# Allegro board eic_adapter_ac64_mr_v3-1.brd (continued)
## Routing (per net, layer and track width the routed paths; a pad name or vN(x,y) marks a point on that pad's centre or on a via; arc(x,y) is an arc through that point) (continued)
SIPMOUT39: length 24.3
  TOP w0.2: J4.35 v1(22.2,65) ; v1(21.4,54.3) Q3.8
  TOP w0.25: C80.2 v1(22.9,47.98)
  LAYER_6 w0.2: v1(22.9,47.98) 21.4,49.48 v1(21.4,54.3) 21.4,55 21.7,55.3 21.7,61.3 21.2,61.8 21.2,62.7 21.8,63.3 21.8,64.09 22.2,64.49 v1(22.2,65)
  BOTTOM w0.25: v1(22.9,47.98) R107.2
SIPMOUT40: length 23.6
  TOP w0.2: v1(32.2,62.5) J4.10 32.2,60.1 33,59.3 Q2.3
  TOP w0.25: C81.2 v1(35.3,46.72)
  LAYER_2 w0.2: v1(35.3,46.72) 34.69,46.72 32,49.4 32,55.9 32.2,56.1 v1(32.2,62.5)
  BOTTOM w0.25: v1(35.3,46.72) R111.2
SIPMOUT41: length 24.4
  TOP w0.2: v1(22.6,63.4) J4.34 22.6,60.1 21.8,59.3 Q3.2
  TOP w0.25: C82.2 v1(22.9,46.72)
  LAYER_8 w0.2: v1(22.6,63.4) 22.6,55.6 23.7,54.5 23.7,47.52 v1(22.9,46.72)
  BOTTOM w0.25: v1(22.9,46.72) R115.2
SIPMOUT42: length 28.6
  TOP w0.2: J4.11 v1(31.8,65) ; v1(32.6,54.9) 32.6,55.41 33,55.81 Q2.8
  TOP w0.25: C83.2 v1(35.2,44.17)
  LAYER_6 w0.2: v1(35.2,44.17) 34.62,44.17 32.6,46.2 v1(32.6,54.9) 32.6,58.7 31.5,59.8 31.5,62.6 32.2,63.3 32.2,63.8 31.8,64.2 v1(31.8,65)
  BOTTOM w0.25: v1(35.2,44.17) R119.2
SIPMOUT43: length 28.5
  TOP w0.2: v1(22.8,54.4) 22.8,54.9 21.8,55.9 Q3.9 ; J4.33 v1(23,65.5)
  TOP w0.25: C84.2 v1(23,44.17)
  LAYER_2 w0.2: v1(23,44.17) 23.9,45.08 23.9,52.8 22.8,53.9 v1(22.8,54.4) 22.8,55.3 22.5,55.6 22.5,62.4 23.4,63.3 23.4,64 23,64.4 v1(23,65.5)
  BOTTOM w0.25: v1(23,44.17) R123.2
SIPMOUT44: length 29.5
  TOP w0.2: v1(31.4,63.4) J4.12 31.4,60.1 32.6,58.9 Q2.4
  TOP w0.25: C85.2 v1(35.2,42.91)
  LAYER_8 w0.2: v1(31.4,63.4) 31.4,59.5 31.9,59 31.9,45.5 34.49,42.91 v1(35.2,42.91)
  BOTTOM w0.25: v1(35.2,42.91) R127.2
SIPMOUT45: length 27.4
  TOP w0.2: v1(23.4,62.5) J4.32 23.4,59.9 22.2,58.7 Q3.1
  TOP w0.25: C86.2 v1(23,42.91)
  LAYER_6 w0.2: v1(23.4,62.5) 23.4,59.4 22.7,58.7 22.7,55.5 23.6,54.6 23.6,53.3 24.2,52.7 24.2,43.6 23.51,42.91 v1(23,42.91)
  BOTTOM w0.25: v1(23,42.91) R131.2
SIPMOUT46: length 32.3
  TOP w0.2: J4.13 v1(31,65.5) ; v1(31.3,55.3) 31.81,55.3 32.6,56.09 Q2.7
  TOP w0.25: C87.2 v1(35.3,41.63)
  LAYER_2 w0.2: v1(31,65.5) 31,64.4 30.6,64 30.6,63.3 31.3,62.6 31.3,61 30.5,60.2 30.5,56.1 v1(31.3,55.3) 31.3,44.9 34.56,41.63 v1(35.3,41.63)
  BOTTOM w0.25: v1(35.3,41.63) R135.2
SIPMOUT47: length 30.9
  TOP w0.2: Q3.10 22.2,56.6 22.4,56.4 v1(23.4,56.4) ; J4.31 v1(23.8,65)
  TOP w0.25: C88.2 v1(22.99,41.63)
  LAYER_6 w0.2: v1(22.99,41.63) 23.03,41.6 23.6,41.6 24.9,42.9 24.9,53.4 24.6,53.7 24.6,55.8 24,56.4 ; v1(23.4,56.4) 24,56.4 ; 24,56.4 24.2,56.6 24.2,62.5 23.5,63.2 23.5,64.1 23.8,64.4 v1(23.8,65)
  BOTTOM w0.25: v1(22.99,41.63) R139.2
SIPMOUT48: length 30.2
  TOP w0.2: Q4.1 30.2,59.6 30.6,60 J4.14 v1(30.6,62.5)
  TOP w0.25: C89.2 v1(35.2,40.37)
  LAYER_6 w0.2: v1(35.2,40.37) 34.63,40.37 31.9,43.1 31.9,58.5 30.6,59.8 v1(30.6,62.5)
  BOTTOM w0.25: v1(35.2,40.37) R81.2
SIPMOUT49: length 31
  TOP w0.2: Q5.4 24.9,59.1 24.2,59.8 J4.30 v1(24.2,63.4)
  TOP w0.25: C90.2 v1(22.99,40.37)
  LAYER_8 w0.2: v1(22.99,40.37) 23.57,40.37 24.6,41.4 24.6,60.9 24.2,61.3 v1(24.2,63.4)
  BOTTOM w0.25: v1(22.99,40.37) R85.2
SIPMOUT50: length 34.3
  TOP w0.2: v1(31.2,56.3) 31.1,56.2 30.6,56.2 30.2,56.6 Q4.10 ; J4.15 v1(30.2,65)
  TOP w0.25: C91.2 v1(35.2,39.09)
  LAYER_6 w0.2: v1(31.2,56.3) 30.7,56.3 ; 30.7,56.3 29.8,57.2 29.8,62.5 30.6,63.3 30.6,63.9 30.2,64.3 v1(30.2,65) ; 30.7,56.3 30.65,56.25 30.65,54.7 31.23,54.12 31.23,42.56 34.69,39.09 v1(35.2,39.09)
  BOTTOM w0.25: v1(35.2,39.09) R89.2
SIPMOUT51: length 33.4
  TOP w0.2: v1(23.9,55.3) 24.64,56.04 24.64,56.34 24.9,56.6 Q5.7 ; J4.29 v1(24.6,65.5)
  TOP w0.25: C92.2 v1(23,39.09)
  LAYER_2 w0.2: v1(23,39.09) 23.5,39.09 25,40.59 25,53.4 23.9,54.5 v1(23.9,55.3) 23.9,55.8 24.25,56.16 24.25,62.55 25,63.3 25,64 24.6,64.4 v1(24.6,65.5)
  BOTTOM w0.25: v1(23,39.09) R93.2
SIPMOUT52: length 34.7
  TOP w0.2: v1(29.8,63.4) J4.16 Q4.2
  TOP w0.25: C93.2 v1(35.2,37.83)
  LAYER_8 w0.2: v1(29.8,63.4) 29.8,56.7 30.7,55.8 30.7,41.7 34.58,37.83 v1(35.2,37.83)
  BOTTOM w0.25: v1(35.2,37.83) R97.2
SIPMOUT53: length 32.4
  TOP w0.2: v1(25,62.5) J4.28 25,60 25.3,59.7 Q5.3
  TOP w0.25: C94.2 v1(23,37.83)
  LAYER_2 w0.2: v1(25,62.5) 25,56.1 24.6,55.7 24.6,54.8 25.6,53.8 25.6,39.9 23.52,37.83 v1(23,37.83)
  BOTTOM w0.25: v1(23,37.83) R101.2
SIPMOUT54: length 37.6
  TOP w0.2: Q4.9 29.8,56.11 30,55.91 v1(30,55.4) ; J4.17 v1(29.4,65.5)
  TOP w0.25: C95.2 v1(35.2,35.28)
  LAYER_2 w0.2: v1(35.2,35.28) 34.69,35.28 30.36,39.62 30.36,55.04 v1(30,55.4) 29.8,55.6 29.8,62.5 29,63.3 29,64 29.4,64.4 v1(29.4,65.5)
  BOTTOM w0.25: v1(35.2,35.28) R105.2
SIPMOUT55: length 37.1
  TOP w0.2: Q5.8 25.3,55.71 25.2,55.61 v1(25.2,55.1) ; J4.27 v1(25.4,65)
  TOP w0.25: C96.2 v1(23,35.28)
  LAYER_6 w0.2: v1(23,35.28) 23.5,35.28 23.51,35.3 23.7,35.3 25.5,37.1 25.5,54.29 25.2,54.59 v1(25.2,55.1) 25.2,61.5 25.7,62 25.7,62.6 25,63.3 25,64 25.4,64.4 v1(25.4,65)
  BOTTOM w0.25: v1(23,35.28) R109.2
SIPMOUT56: length 38.4
  TOP w0.2: Q4.3 29.4,59.5 29,59.9 J4.18 v1(29,62.5)
  TOP w0.25: C97.2 v1(35.21,34.02)
  LAYER_2 w0.2: v1(35.21,34.02) 33.88,34.02 28.06,39.84 28.06,54.06 28.4,54.4 28.4,55.8 29,56.4 v1(29,62.5)
  BOTTOM w0.25: v1(35.21,34.02) R113.2
SIPMOUT57: length 37.4
  TOP w0.2: v1(25.8,63.4) J4.26 25.8,59.8 25.7,59.7 Q5.2
  TOP w0.25: C103.2 v1(23,34.02)
  LAYER_8 w0.2: v1(23,34.02) 23.5,34.02 25.8,36.32 v1(25.8,63.4)
  BOTTOM w0.25: v1(23,34.02) R117.2
SIPMOUT58: length 41.2
  TOP w0.2: Q4.8 29.4,55.6 v1(29,55.2) ; J4.19 v1(28.6,65)
  TOP w0.25: C104.2 v1(35.2,32.74)
  LAYER_6 w0.2: v1(28.6,65) 28.6,64.4 29,64 29,63.3 28.3,62.6 28.3,61.7 29,61 v1(29,55.2) 29,54.5 30.2,53.3 30.2,36.9 34.36,32.74 v1(35.2,32.74)
  BOTTOM w0.25: v1(35.2,32.74) R121.2
SIPMOUT59: length 40
  TOP w0.2: v1(26.5,55.3) 25.7,56.1 Q5.9 ; J4.25 v1(26.2,65.5)
  TOP w0.25: v1(23,32.74) C105.2
  LAYER_2 w0.2: v1(23,32.74) 23.5,32.74 26.5,35.74 v1(26.5,55.3) 25.8,56 25.8,62.5 26.6,63.3 26.6,64 26.2,64.4 v1(26.2,65.5)
  BOTTOM w0.25: R125.2 v1(23,32.74)
SIPMOUT60: length 42.5
  TOP w0.2: Q4.4 29,59.3 28.2,60.1 J4.20 v1(28.2,63.4)
  TOP w0.25: v1(35.21,31.48) 35.1,31.48 35.09,31.47 C106.2
  LAYER_8 w0.2: v1(35.21,31.48) 34.62,31.48 27.9,38.2 27.9,53.5 28.4,54 28.4,60.2 28.2,60.4 v1(28.2,63.4)
  BOTTOM w0.25: v1(35.21,31.48) R129.2
SIPMOUT61: length 39.2
  TOP w0.2: v1(26.6,62.5) J4.24 26.6,59.6 26.1,59.1 Q5.1
  TOP w0.25: C107.2 v1(23,31.48)
  LAYER_6 w0.2: v1(26.6,62.5) 26.6,61.8 25.85,61.05 25.85,54.65 26.4,54.1 26.4,34.3 23.57,31.48 v1(23,31.48)
  BOTTOM w0.25: v1(23,31.48) R133.2
SIPMOUT62: length 45.4
  TOP w0.2: v1(27.7,54.9) 29,56.2 Q4.7 ; J4.21 v1(27.8,65.5)
  TOP w0.25: C140.2 v1(35.2,30.2)
  LAYER_6 w0.2: v1(35.2,30.2) 34.3,30.2 27.34,37.16 27.34,54.54 v1(27.7,54.9) 27.7,56 28.4,56.7 28.4,60.2 27.4,61.2 27.4,64 27.8,64.4 v1(27.8,65.5)
  BOTTOM w0.25: v1(35.2,30.2) R137.2
SIPMOUT63: length 42.4
  TOP w0.2: J4.23 v1(27,65) ; v1(27,56.2) 26.3,56.2 26.1,56.4 Q5.10
  TOP w0.25: C141.2 v1(23,30.2)
  LAYER_2 w0.2: v1(23,30.2) 23.51,30.2 23.51,30.2 24,30.2 27.1,33.3 27.1,55.6 27,55.7 v1(27,56.2) 27,56.7 26.7,57 26.7,60.6 27.3,61.2 27.3,64.2 27,64.5 v1(27,65)
  BOTTOM w0.25: v1(23,30.2) R141.2
VB0: length 71.2
  TOP w0.2: J4.1 35.8,65.75 v1(36.12,65.42)
  TOP w0.5: C100.2 v1(31.1,7.3) L1.1
  LAYER_8 w0.5: v1(36.12,65.42) 37.28,65.42 39.2,63.5 39.2,9.6 36.44,6.84 31.56,6.84 v1(31.1,7.3)
VB1: length 68.6
  TOP w0.2: v1(36.3,61.7) 35.78,61.17 J4.2
  TOP w0.5: C101.2 v1(31.1,5.7) L4.1
  LAYER_4 w0.5: v1(31.1,5.7) 31.75,5.7 32.15,5.3 36.2,5.3 39.2,8.3 39.2,60.4 37.9,61.7 v1(36.3,61.7)
VB2: length 70.7
  TOP w0.2: J4.3 35,65 v1(35.1,64.9)
  TOP w0.5: C102.2 v1(31.2,8.8) 30.13,8.8 L5.1
  LAYER_6 w0.5: v1(35.1,64.9) 35.8,64.2 38,64.2 39.2,63 39.2,11 36.5,8.3 31.7,8.3 v1(31.2,8.8)
VB3: length 73.5
  TOP w0.25: v1(36.2,63) 35.32,63 34.6,62.28 J4.4
  TOP w0.5: L6.1 v1(31.1,4.1) C142.2
  LAYER_2 w0.5: v1(31.1,4.1) 31.75,4.1 32.15,3.7 35.4,3.7 39.2,7.5 39.2,62.4 38.6,63 v1(36.2,63)
VB4: length 69.4
  TOP w0.2: J4.77 v1(5.4,65)
  TOP w0.5: L7.1 v1(7,7.1) 6.8,7.3 C143.2
  LAYER_2 w0.5: v1(5.4,65) 4.6,64.2 2.8,64.2 1.1,62.5 1.1,9.2 3.2,7.1 v1(7,7.1)
VB5: length 68.3
  TOP w0.2: J4.78 v1(5,62.43)
  TOP w0.5: L8.1 v1(7,5.5) 6.6,5.9 C144.2
  LAYER_4 w0.5: v1(5,62.43) 2.33,62.43 1.1,61.2 1.1,7.6 3.2,5.5 v1(7,5.5)
VB6: length 66.8
  TOP w0.2: J4.79 v1(4.6,65.5)
  TOP w0.5: L9.1 v1(6.9,8.7) C145.2
  LAYER_8 w0.4: v1(4.6,65.5) 3.1,65.5 0.9,63.3 0.9,11.7
  LAYER_8 w0.5: v1(6.9,8.7) 3.9,8.7 0.9,11.7
VB7: length 66.9
  TOP w0.3: v1(3.3,61.2) 4.18,61.2 J4.80
  TOP w0.5: L10.1 v1(7.06,3.9) 6.6,3.9 6,4.5 C146.2
  LAYER_6 w0.5: v1(3.3,61.2) 2.2,61.2 0.9,59.9 0.9,6.4 3.2,4.1 6.21,4.1 6.41,3.9 v1(7.06,3.9)
VBIAS_0: length 2.7
  TOP w0.5: J2.20 27.25,7.42 27.37,7.3 L1.2
VBIAS_1: length 3.6
  TOP w0.5: J2.19 25.71,5.01 26.36,5.66 27.26,5.66 27.3,5.7 L4.2
VBIAS_2: length 5.6
  TOP w0.5: L5.2 27.32,8.9 27.02,9.2 24.8,9.2 24.45,8.85 J2.18
VBIAS_3: length 5.9
  TOP w0.5: L6.2 26.97,2.7 25,2.7 24.45,3.25 J2.17
VBIAS_4: length 17.1
  TOP w0.5: 23.18,7.42 23.2,7.45 v1(23.2,9) ; v1(10.4,7.1) L7.2
  BOTTOM w0.5: v1(10.4,7.1) 11.05,7.1 11.85,6.3 21.15,6.3 23.2,8.35 v1(23.2,9)
VBIAS_5: length 17.1
  TOP w0.5: v1(10.5,5.5) L8.2 ; J2.15 23.2,4.35 v1(23.2,2.7)
  BOTTOM w0.5: v1(23.2,2.7) 23.2,3.7 21.5,5.4 11.25,5.4 11.15,5.5 v1(10.5,5.5)
VBIAS_6: length 15.2
  TOP w0.5: v1(21.9,9) 21.9,7.43 21.91,7.42 ; L9.2 v1(10.4,8.7)
  BOTTOM w0.5: v1(21.9,9) 20.2,7.3 12.45,7.3 11.05,8.7 v1(10.4,8.7)
VBIAS_7: length 15.5
  TOP w0.5: v1(21.9,2.7) 21.9,4.37 J2.13 ; v1(10.8,3.9) L10.2
  BOTTOM w0.5: v1(21.9,2.7) 21.9,3.35 20.65,4.6 12.15,4.6 11.45,3.9 v1(10.8,3.9)
VLOGIC: length 74.9
  TOP w0.2: IC4.20 36.9,18.8 v1(37.5,18.2) ; IC1.6 3.3,17.2 3.1,17 v1(3.1,16.5) ; L2.1 11.44,16.1 12.54,17.2 IC2.6 ; IC3.6 20.9,17.2 20.6,16.9 v1(18.7,16.9) 18.7,17.4 18.1,18 IC2.18 ; IC3.18 27.1,18 27.7,17.4 v1(27.7,16.9) 29,16.9 29.3,17.2 IC4.6 ; v1(36.7,16.9) 36.7,17.45 36.15,18 IC4.18 ; IC1.18 9.05,18 9.8,17.25 v1(9.8,16.9) ; IC3.20 27.2,18.8 27.3,18.9 v1(27.8,18.9) ; IC1.20 9.7,18.8 10,18.5 v1(10.5,18.5) ; IC2.20 v1(18.9,18.8)
  TOP w0.3: v1(9.8,16.9) 9.7,16.8 C35.2 L2.1
  TOP w0.4: C34.2 v1(18.7,16.9) ; v1(36.7,16.9) 36.9,16.7 C41.2
  TOP w0.5: v1(27.7,16.9) C40.2
  LAYER_8 w0.4: v1(18.7,16.9) 18.7,18 18.9,18.2 v1(18.9,18.8) ; v1(27.8,18.9) 27.8,18.3 27.7,18.2 v1(27.7,16.9)
  LAYER_8 w0.5: v1(10.5,18.5) 10.5,17.6 v1(9.8,16.9)
  BOTTOM w0.4: v1(36.7,16.9) 36.7,17.4 36.9,17.6 36.9,17.6 v1(37.5,18.2)
  BOTTOM w0.6: v1(36.7,16.9) 36.2,16.4 29.9,16.4 29.4,16.9 v1(27.7,16.9) 25.2,16.9 24.7,16.4 19.85,16.4 19.35,16.9 v1(18.7,16.9) 16.3,16.9 15.84,16.44 10.96,16.44 10.5,16.9 v1(9.8,16.9) 7.6,16.9 7.2,16.5 v1(3.1,16.5)
VTRIM-0: length 47.8
  TOP w0.2: v1(12.6,12.5) 13.15,13.05 RN6.5
  TOP w0.25: v1(19.6,52.2) 19.3,52.2 C2.2
  LAYER_4 w0.2: v1(19.6,52.2) 18.5,52.2 17.46,51.16 16.66,51.16 11.3,45.8 11.3,30.6 11.8,30.1 11.8,27.8 11.3,27.3 11.3,23.8 12.6,22.5 v1(12.6,12.5)
  BOTTOM w0.25: C2.2 19.25,51.8 19.5,52.05 19.5,52.1 v1(19.6,52.2)
VTRIM-1: length 37.5
  TOP w0.2: v1(9.7,23.5) 8.57,23.5 8.35,23.28 RN3.5
  TOP w0.25: C3.2 2.89,51.8 v1(2.1,51.8)
  LAYER_4 w0.2: v1(2.1,51.8) 3,51.8 3.64,51.16 3.64,50.66 4.4,49.9 6.2,49.9 10.4,45.7 10.4,30.5 10,30.1 10,27.9 10.4,27.5 10.4,24.2 v1(9.7,23.5)
  BOTTOM w0.25: R8.1 v1(2.1,51.8)
VTRIM-2: length 35.3
  TOP w0.2: v1(12.3,24) 12.8,24 13.25,23.55 RN5.8
  TOP w0.25: C4.2 19.18,50.8 v1(19.61,50.8)
  LAYER_4 w0.2: v1(12.3,24) 11.85,24.45 11.85,27.14 12.3,27.6 12.3,30.9 11.8,31.4 11.8,45 16.69,49.89 17.89,49.89 18.8,50.8 v1(19.61,50.8)
  BOTTOM w0.25: C4.2 19.23,50.52 19.5,50.8 v1(19.61,50.8)
VTRIM-3: length 47.5
  TOP w0.2: RN4.8 8.15,13.45 8.4,13.2 v1(8.4,11.7)
  TOP w0.25: v1(2.2,50.5) 2.87,50.5 C5.2
  LAYER_4 w0.2: v1(8.4,11.7) 8.76,12.05 8.76,23.66 9.8,24.7 9.8,27.3 9.4,27.7 9.4,31.1 9.7,31.4 9.7,44.9 6,48.6 4.2,48.6 3.6,49.2 3.6,49.7 2.8,50.5 v1(2.2,50.5)
  BOTTOM w0.25: C5.2 2.23,50.53 v1(2.2,50.5)
VTRIM-4: length 45.5
  TOP w0.2: v1(13.3,11.9) 13.3,12.2 13.65,12.55 RN6.6
  TOP w0.25: C6.2 19.16,49.26 19.5,49.6 v1(19.6,49.6)
  LAYER_4 w0.2: v1(19.6,49.6) 18.8,49.6 17.82,48.62 16.62,48.62 12.4,44.4 12.4,32 12.7,31.7 12.7,27.3 12.4,27 12.4,25 13.2,24.2 13.2,12.5 13.3,12.4 v1(13.3,11.9)
  BOTTOM w0.25: C6.2 19.25,49.6 v1(19.6,49.6)
VTRIM-5: length 32.6
  TOP w0.2: RN3.6 7.85,23.55 9.2,24.9 v1(9.2,26.3)
  TOP w0.25: C7.2 v1(2.2,49.26)
  LAYER_4 w0.2: v1(9.2,26.3) 9.2,26.8 8.8,27.2 8.8,44.4 5.8,47.4 4.1,47.4 3,48.5 3,49 2.75,49.26 v1(2.2,49.26)
  BOTTOM w0.25: v1(2.2,49.26) C7.2
VTRIM-6: length 31.4
  TOP w0.2: v1(13,26.4) 13,24.8 13.75,24.05 RN5.7
  TOP w0.25: v1(19.6,48.3) 19.5,48.2 19.12,48.2 C8.2
  LAYER_4 w0.2: v1(13,26.4) 13,26.9 13.2,27.1 13.2,43.9 16.65,47.35 18.05,47.35 19,48.3 v1(19.6,48.3)
  BOTTOM w0.25: C8.2 19.29,47.98 v1(19.6,48.3)
VTRIM-7: length 41.8
  TOP w0.2: v1(7.8,12.4) 7.8,12.6 7.65,12.75 RN4.7
  TOP w0.25: v1(2.2,47.98) C9.2
  LAYER_4 w0.2: v1(7.8,12.4) 7.8,16.7 8.15,17.05 8.15,23.95 8.6,24.4 8.6,26 8.2,26.4 8.2,43.2 5.3,46.1 4.09,46.1 v1(2.2,47.98)
  BOTTOM w0.25: C9.2 v1(2.2,47.98)
VTRIM-8: length 41.1
  TOP w0.2: RN6.7 14.15,12.35 v1(14.2,12.3)
  TOP w0.25: C10.2 19.19,47 v1(19.61,47)
  LAYER_4 w0.2: v1(19.61,47) 18.8,47 17.9,46.1 16.9,46.1 13.7,42.9 13.7,25.7 13.4,25.4 13.4,24.7 13.8,24.3 13.8,16.7 14.2,16.3 v1(14.2,12.3)
  BOTTOM w0.25: C10.2 19.19,47 v1(19.61,47)
VTRIM-9: length 28.8
  TOP w0.2: RN3.7 7.35,24.05 v1(7.9,24.6)
  TOP w0.25: C11.2 v1(2.2,46.72)
  LAYER_4 w0.2: v1(2.2,46.72) 2.2,46.21 3.61,44.8 5.2,44.8 7.7,42.3 7.7,25.7 7.9,25.5 v1(7.9,24.6)
  BOTTOM w0.25: v1(2.2,46.72) C11.2
VTRIM-10: length 26.8
  TOP w0.2: v1(14.2,24.8) 14.2,24.3 14.25,24.25 RN5.6
  TOP w0.25: C12.2 19.23,44.51 v1(19.6,44.51)
  LAYER_4 w0.2: v1(14.2,24.8) 14.2,41.1 16.64,43.54 17.64,43.54 18.61,44.51 v1(19.6,44.51)
  BOTTOM w0.25: C12.2 18.9,44.2 19.21,44.51 v1(19.6,44.51)
VTRIM-11: length 39.1
  TOP w0.2: RN4.6 v1(7.15,11.7)
  TOP w0.25: v1(2.2,44.17) C13.2
  LAYER_4 w0.2: v1(7.15,11.7) 7.15,13.95 6.9,14.2 6.9,23.2 7.2,23.5 7.2,40.6 5.5,42.3 4.2,42.3 3.6,42.9 3.6,43.38 2.8,44.17 v1(2.2,44.17)
  BOTTOM w0.25: C13.2 v1(2.2,44.17)
VTRIM-12: length 38.3
  TOP w0.2: v1(14.8,11.8) 14.8,12.47 14.65,12.62 RN6.8
  TOP w0.25: C14.2 19.2,42.91 19.5,43.2 v1(19.7,43.2)
  LAYER_4 w0.2: v1(14.8,11.8) 14.8,16.4 15.1,16.7 15.1,25.3 14.7,25.7 14.7,40.5 16.47,42.27 17.97,42.27 18.9,43.2 v1(19.7,43.2)
  BOTTOM w0.25: v1(19.7,43.2) 19.2,43.2 C14.2
VTRIM-13: length 24.5
  TOP w0.2: v1(6.6,26.3) 6.6,23.53 6.85,23.28 RN3.8
  TOP w0.25: C15.2 v1(2.1,42.91)
  LAYER_4 w0.2: v1(2.1,42.91) 3.91,41.1 5.3,41.1 6.6,39.8 v1(6.6,26.3)
  BOTTOM w0.25: v1(2.1,42.91) C15.2
VTRIM-14: length 24.4
  TOP w0.2: RN5.5 14.75,25.15 15.3,25.7 v1(15.3,26.4)
  TOP w0.25: C16.2 19.43,41.63 v1(19.7,41.9)
  LAYER_4 w0.2: v1(19.7,41.9) 18.9,41.9 18,41 16.4,41 15.3,39.9 v1(15.3,26.4)
  BOTTOM w0.25: C16.2 19.23,41.63 19.5,41.9 v1(19.7,41.9)
VTRIM-15: length 34.9
  TOP w0.2: v1(6.5,12.4) 6.5,12.8 6.65,12.95 RN4.5
  TOP w0.25: v1(2.1,41.63) C17.2
  LAYER_4 w0.2: v1(6.5,12.4) 6.5,13.6 6.2,13.9 6.2,23.3 6.6,23.7 6.6,25.3 6,25.9 6,39.1 5.4,39.7 4.04,39.7 v1(2.1,41.63)
  BOTTOM w0.25: C17.2 v1(2.1,41.63)
VTRIM-16: length 34.2
  TOP w0.2: v1(15.5,12.3) 15.7,12.5 RN8.5
  TOP w0.25: v1(19.7,40.6) 19.46,40.37 C18.2
  LAYER_4 w0.2: v1(15.5,12.3) 15.5,16 15.6,16.1 15.6,25.1 15.9,25.4 15.9,39.3 16.33,39.73 18.03,39.73 18.9,40.6 v1(19.7,40.6)
  BOTTOM w0.25: C18.2 19.27,40.37 19.5,40.6 v1(19.7,40.6)
VTRIM-17: length 21.5
  TOP w0.2: RN1.5 5.75,23.55 5.9,23.7 v1(5.9,24.6)
  TOP w0.25: v1(2.1,40.37) 2.11,40.37 C19.2
  LAYER_4 w0.2: v1(2.1,40.37) 4.06,38.4 5.2,38.4 5.5,38.1 5.5,25 v1(5.9,24.6)
  BOTTOM w0.25: v1(2.1,40.37) R10.1
VTRIM-18: length 19.9
  TOP w0.2: RN7.8 15.85,23.45 16.2,23.8 v1(16.2,24.3)
  TOP w0.25: v1(19.61,39.4) 19.5,39.4 19.2,39.09 C20.2
  LAYER_4 w0.2: v1(16.2,24.3) 16.2,24.8 16.4,25 16.4,36.4 19.05,39.05 19.25,39.05 v1(19.61,39.4)
  BOTTOM w0.25: v1(19.61,39.4) 19.21,39.4 C20.2
VTRIM-19: length 32.8
  TOP w0.2: RN2.8 5.75,13.02 5.9,12.87 v1(5.9,11.7)
  TOP w0.25: v1(2.1,39.09) C21.2
  LAYER_8 w0.2: v1(5.9,11.7) 5.9,13.3 4.5,14.7 4.5,22.5 3.3,23.7 3.3,38.6 2.8,39.09 v1(2.1,39.09)
  BOTTOM w0.25: C21.2 v1(2.1,39.09)
VTRIM-20: length 31.2
  TOP w0.2: RN8.6 16.2,12.3 16.1,12.2 v1(16.1,11.7)
  TOP w0.25: v1(19.7,38.1) 19.43,37.83 C22.2
  LAYER_8 w0.2: v1(16.1,11.7) 16.1,17.2 18.7,19.8 18.7,37.1 v1(19.7,38.1)
  BOTTOM w0.25: C22.2 19.23,37.83 19.5,38.1 v1(19.7,38.1)
VTRIM-21: length 18.2
  TOP w0.2: RN1.6 5.25,24.15 4.7,24.7 v1(4.7,26.2)
  TOP w0.25: C23.2 v1(2,37.83)
  LAYER_6 w0.2: v1(2,37.83) 2.9,36.92 2.9,36.6 3.8,35.7 3.8,28.1 4.7,27.2 v1(4.7,26.2)
  BOTTOM w0.25: v1(2,37.83) C23.2
VTRIM-22: length 16.2
  TOP w0.2: RN7.7 16.35,23.35 17.1,24.1 v1(17.1,26.4)
  TOP w0.25: v1(19.6,35.6) 19.5,35.6 19.18,35.28 C24.2
  LAYER_4 w0.2: v1(17.1,26.4) 17.1,27.6 17.55,28.05 17.55,34.26 18.9,35.6 v1(19.6,35.6)
  BOTTOM w0.25: v1(19.6,35.6) 19.22,35.6 C24.2
VTRIM-23: length 27.5
  TOP w0.2: RN2.7 v1(5.25,12.3)
  TOP w0.25: v1(2.1,35.28) C25.2
  LAYER_4 w0.2: v1(2.1,35.28) 2.82,35.28 3.8,34.3 3.8,28.4 4.1,28.1 4.1,25.6 4.7,25 4.7,16.5 5.25,15.95 v1(5.25,12.3)
  BOTTOM w0.25: C25.2 v1(2.1,35.28)
VTRIM-24: length 26.5
  TOP w0.2: v1(16.8,12.2) 16.7,12.3 RN8.7
  TOP w0.25: C26.2 19.21,34.02 v1(19.6,34.4)
  LAYER_4 w0.2: v1(16.8,12.2) 16.8,14.9 17.3,15.4 17.3,24.6 18.04,25.34 18.04,33.64 18.8,34.4 v1(19.6,34.4)
  BOTTOM w0.25: C26.2 19.21,34.02 v1(19.6,34.4)
VTRIM-25: length 14.3
  TOP w0.2: RN1.7 4.75,23.85 v1(3.9,24.7)
  TOP w0.25: C27.2 v1(2.1,34.02)
  LAYER_4 w0.2: v1(3.9,24.7) 3.55,25.05 3.55,27.86 3.2,28.2 3.2,33.4 3.25,33.45 2.68,34.02 v1(2.1,34.02)
  BOTTOM w0.25: v1(2.1,34.02) C27.2
VTRIM-26: length 13.3
  TOP w0.2: RN7.6 16.85,23.15 v1(18.05,24.35)
  TOP w0.25: C28.2 19.23,33.08 v1(19.58,33.08)
  LAYER_4 w0.2: v1(18.05,24.35) 18.56,24.86 18.56,32.56 19.08,33.08 v1(19.58,33.08)
  BOTTOM w0.25: C28.2 18.9,32.77 19.21,33.08 v1(19.58,33.08)
VTRIM-27: length 25.5
  TOP w0.2: v1(4.4,11.7) 4.4,12.3 4.75,12.65 RN2.6
  TOP w0.25: v1(2.1,32.74) C29.2
  LAYER_4 w0.2: v1(4.4,11.7) 4.4,15.8 4.2,16 4.2,23 3.1,24.1 3.1,27 2.7,27.4 2.7,32.15 v1(2.1,32.74)
  BOTTOM w0.25: C29.2 v1(2.1,32.74)
VTRIM-28: length 24.3
  TOP w0.2: v1(17.5,11.7) 17.5,12.3 17.2,12.6 RN8.8
  TOP w0.25: C30.2 19.07,31.47 19.5,31.9 v1(19.6,31.9)
  LAYER_4 w0.2: v1(17.5,11.7) 17.5,14.5 18,15 18,22.8 19.07,23.87 19.07,31.37 v1(19.6,31.9)
  BOTTOM w0.25: v1(19.6,31.9) 19.33,31.9 R54.1
VTRIM-29: length 11.3
  TOP w0.2: v1(2.5,26.3) 2.5,25.03 4.25,23.28 RN1.8
  TOP w0.25: C31.2 v1(2.1,31.48)
  LAYER_6 w0.2: v1(2.1,31.48) 2.7,30.88 2.7,29.6 2.5,29.4 v1(2.5,26.3)
  BOTTOM w0.25: v1(2.1,31.48) C31.2
VTRIM-30: length 10.6
  TOP w0.2: v1(19.6,30.54) 19.6,24.62 17.78,22.8 RN7.5
  TOP w0.25: v1(19.6,30.54) 19.23,30.54 C32.2
  BOTTOM w0.25: C32.2 18.9,30.23 19.21,30.54 v1(19.6,30.54)
VTRIM-31: length 21.8
  TOP w0.2: v1(3.7,12.3) 4.25,12.85 RN2.5 ; C99.2 v1(2.1,30.2)
  LAYER_4 w0.2: v1(2.1,30.2) 2.1,29.7 1.9,29.5 1.9,22.2 3.7,20.4 v1(3.7,12.3)
  BOTTOM w0.25: R66.1 2.11,30.21 2.1,30.2 v1(2.1,30.2)
VTRIM-32: length 37.6
  TOP w0.2: v1(29.8,23.8) 30.73,23.8 31.25,23.28 RN15.8
  TOP w0.25: C39.2 v1(38,51.8)
  LAYER_4 w0.2: v1(38,51.8) 36.59,51.8 35.96,51.16 34.56,51.16 29.6,46.2 29.6,30.8 29.9,30.5 29.9,28.5 29.4,28 29.4,24.2 v1(29.8,23.8)
  BOTTOM w0.25: v1(38,51.8) C39.2
VTRIM-33: length 48.8
  TOP w0.2: C43.2 20.86,51.8 20.57,51.5 v1(20.37,51.5) ; RN14.8 26.2,12.62 26.62,12.2 v1(26.9,12.2)
  LAYER_4 w0.2: v1(26.9,12.2) 26.9,15.2 27,15.3 27,22 28.7,23.7 28.7,28.1 28.2,28.6 28.2,30.3 28.8,30.9 28.8,46.1 23.7,51.2 21.9,51.2 21.6,51.5 v1(20.37,51.5)
  BOTTOM w0.2: v1(20.37,51.5) 20.6,51.5 20.89,51.8 C43.2
VTRIM-34: length 45.9
  TOP w0.2: RN16.5 30.8,13.1 v1(30.3,12.6)
  TOP w0.25: v1(37.9,50.52) C45.2
  LAYER_4 w0.2: v1(30.3,12.6) 30.3,18.9 30.5,19.1 30.5,24.1 29.9,24.7 29.9,27.4 30.4,27.9 30.4,45.7 34.59,49.89 36.09,49.89 36.73,50.52 v1(37.9,50.52)
  BOTTOM w0.25: C45.2 v1(37.9,50.52)
VTRIM-35: length 35.3
  TOP w0.2: v1(27.9,24.3) 27.55,23.95 27.14,23.95 26.25,23.05 RN13.5
  TOP w0.25: v1(20.4,50.3) 20.87,50.3 C47.2
  LAYER_4 w0.2: v1(20.4,50.3) 21.6,50.3 22,49.9 23.7,49.9 28,45.6 28,31.2 27.6,30.8 27.6,28.2 28.1,27.7 28.1,25.2 27.9,25 v1(27.9,24.3)
  BOTTOM w0.25: v1(20.4,50.3) 20.62,50.52 C47.2
VTRIM-36: length 33.4
  TOP w0.2: RN15.7 31.75,23.65 v1(30.5,24.9)
  TOP w0.25: C49.2 v1(38,49.26)
  LAYER_4 w0.2: v1(30.5,24.9) 30.5,27.3 31,27.8 31,44.8 34.82,48.62 36.12,48.62 36.75,49.26 v1(38,49.26)
  BOTTOM w0.25: v1(38,49.26) C49.2
VTRIM-37: length 45.4
  TOP w0.2: RN14.7 25.7,12.2 v1(26.05,11.85)
  TOP w0.25: v1(20.39,48.91) 20.74,49.26 C51.2
  LAYER_4 w0.2: v1(26.05,11.85) 26.05,15.55 26.5,16 26.5,22.6 27.1,23.2 27.1,25.2 27.5,25.6 27.5,27.3 27,27.8 27,45.2 23.6,48.6 21.9,48.6 21.59,48.91 v1(20.39,48.91)
  BOTTOM w0.25: v1(20.39,48.91) 20.75,48.91 C51.2
VTRIM-38: length 43.7
  TOP w0.2: RN16.6 31.75,12.62 v1(31.03,11.9)
  TOP w0.25: v1(38,47.98) C53.2
  LAYER_4 w0.2: v1(31.03,11.9) 31.03,27.03 31.6,27.6 31.6,44 34.95,47.35 36.55,47.35 37.19,47.98 v1(38,47.98)
  BOTTOM w0.25: C53.2 v1(38,47.98)
VTRIM-39: length 31.3
  TOP w0.2: v1(26.9,26.2) 26.9,24.5 25.75,23.35 RN13.6
  TOP w0.25: v1(20.4,47.8) 20.94,47.8 21.1,47.96 C55.2
  LAYER_4 w0.2: v1(26.9,26.2) 26.9,27 26.4,27.5 26.4,44.5 23.5,47.4 22.2,47.4 21.8,47.8 v1(20.4,47.8)
  BOTTOM w0.25: v1(20.4,47.8) 20.91,47.8 C55.2
VTRIM-40: length 29.5
  TOP w0.2: v1(31.7,25.5) 31.7,24.5 32.25,23.95 RN15.6
  TOP w0.25: C57.2 v1(38,46.72)
  LAYER_4 w0.2: v1(31.7,25.5) 31.7,27 32.21,27.51 32.21,42.61 35.8,46.2 37.48,46.2 v1(38,46.72)
  BOTTOM w0.25: v1(38,46.72) C57.2
VTRIM-41: length 42.9
  TOP w0.2: RN14.6 v1(25.2,11.3)
  TOP w0.25: v1(20.4,46.4) 20.67,46.67 21.05,46.67 C59.2
  LAYER_4 w0.2: v1(20.4,46.4) 21.4,46.4 21.8,46 23.3,46 25.8,43.5 25.8,27.3 26.2,26.9 26.2,23.6 26.03,23.43 26.03,16.53 25.2,15.7 v1(25.2,11.3)
  BOTTOM w0.25: v1(20.4,46.4) 20.83,46.4 21.1,46.67 C59.2
VTRIM-42: length 39.8
  TOP w0.2: v1(32,12) 32.25,12.25 RN16.7
  TOP w0.25: v1(38,44.17) C61.2
  LAYER_4 w0.2: v1(32,12) 32,15.4 31.6,15.8 31.6,20.7 32.4,21.5 32.4,26.9 32.7,27.2 32.7,42 34.24,43.54 36.54,43.54 37.17,44.17 v1(38,44.17)
  BOTTOM w0.25: C61.2 v1(38,44.17)
VTRIM-43: length 26.1
  TOP w0.2: v1(25.45,24.3) 25.45,23.8 25.25,23.6 RN13.7
  TOP w0.25: v1(20.4,43.8) 20.77,44.17 C63.2
  LAYER_4 w0.2: v1(25.45,24.3) 25.45,25.05 25.6,25.2 25.6,26.6 25.2,27 25.2,40.8 23.7,42.3 22.5,42.3 21,43.8 v1(20.4,43.8)
  BOTTOM w0.25: v1(20.4,43.8) 20.72,43.8 C63.2
VTRIM-44: length 26.1
  TOP w0.2: v1(33,24.2) 33,23.53 32.75,23.28 RN15.5
  TOP w0.25: C65.2 v1(38,42.91)
  LAYER_4 w0.2: v1(38,42.91) 37,42.91 36.37,42.27 34.17,42.27 33.3,41.4 33.3,26.9 32.85,26.45 32.85,24.85 33,24.7 v1(33,24.2)
  BOTTOM w0.25: v1(38,42.91) C65.2
VTRIM-45: length 36.2
  TOP w0.2: RN14.5 24.7,12.4 v1(24.5,12.2)
  TOP w0.25: C67.2 20.77,42.57 v1(20.43,42.57)
  LAYER_4 w0.2: v1(24.5,12.2) 24.5,15.9 24.8,16.2 24.8,25.3 25.1,25.6 25.1,26.3 24.7,26.7 24.7,39.99 23.59,41.1 22.5,41.1 21.03,42.57 v1(20.43,42.57)
  BOTTOM w0.25: v1(20.43,42.57) 20.79,42.57 21.1,42.88 C67.2
VTRIM-46: length 38.1
  TOP w0.2: RN16.8 32.75,12.45 32.8,12.4 v1(32.8,11.5)
  TOP w0.25: v1(38,41.63) C69.2
  LAYER_4 w0.2: v1(32.8,11.5) 32.8,16 32.1,16.7 32.1,20.2 33.6,21.7 33.6,24.96 33.4,25.16 33.4,26.2 33.9,26.7 33.9,40.4 34.5,41 36.2,41 36.84,41.63 v1(38,41.63)
  BOTTOM w0.25: C69.2 v1(38,41.63)
VTRIM-47: length 22.9
  TOP w0.2: RN13.8 24.75,24.99 24.14,25.6 v1(24.14,26.1)
  TOP w0.25: C71.2 20.83,41.63 20.5,41.3 v1(20.4,41.3)
  LAYER_4 w0.2: v1(20.4,41.3) 21,41.3 22.5,39.8 23.53,39.8 24.14,39.19 v1(24.14,26.1)
  BOTTOM w0.25: v1(20.4,41.3) 20.76,41.3 R139.1
VTRIM-48: length 22.6
  TOP w0.2: RN17.8 33.85,24.75 34.1,25 v1(34.1,25.6)
  TOP w0.25: C42.2 v1(38,40.37)
  LAYER_4 w0.2: v1(38,40.37) 36.77,40.37 36.13,39.73 34.83,39.73 34.45,39.35 34.45,26.46 34.1,26.1 v1(34.1,25.6)
  BOTTOM w0.25: v1(38,40.37) C42.2
VTRIM-49: length 34.4
  TOP w0.2: RN10.8 23.7,12.3 23.9,12.1 v1(23.9,11.6)
  TOP w0.25: C44.2 20.77,40.03 v1(20.4,40.03)
  LAYER_4 w0.2: v1(23.9,11.6) 23.9,16.3 24.2,16.6 24.2,24.6 23.4,25.4 23.4,26.5 23.6,26.7 23.6,38.28 23.38,38.5 22.6,38.5 21.07,40.03 v1(20.4,40.03)
  BOTTOM w0.25: C44.2 21.1,40.34 20.79,40.03 v1(20.4,40.03)
VTRIM-50: length 31.9
  TOP w0.2: v1(33.5,12.2) 33.65,12.35 RN18.5
  TOP w0.25: v1(38,39.09) C46.2
  LAYER_4 w0.2: v1(38,39.09) 37.3,39.09 36.6,38.4 36.6,36.9 35.8,36.1 35.8,27.9 34.9,27 34.9,25.4 34.4,24.9 34.4,20.7 33.5,19.8 v1(33.5,12.2)
  BOTTOM w0.25: C46.2 v1(38,39.09)
VTRIM-51: length 19.3
  TOP w0.2: v1(23.35,24.35) 23.75,23.95 RN9.5
  TOP w0.25: v1(20.4,38.7) 20.5,38.7 20.89,39.09 C48.2
  LAYER_8 w0.2: v1(20.4,38.7) 20.9,38.7 21.3,38.3 21.3,35.6 22.2,34.7 22.2,28.5 23.35,27.35 v1(23.35,24.35)
  BOTTOM w0.25: v1(20.4,38.7) 20.7,38.7 C48.2
VTRIM-52: length 18.3
  TOP w0.2: v1(35,24.5) 34.35,23.85 RN17.7
  TOP w0.25: C50.2 v1(38,37.83)
  LAYER_6 w0.2: v1(35,24.5) 35,26.2 36.62,27.82 36.62,36.45 v1(38,37.83)
  BOTTOM w0.25: v1(38,37.83) C50.2
VTRIM-53: length 29.8
  TOP w0.2: RN10.7 v1(23.2,12)
  TOP w0.25: C52.2 21.1,37.78 20.82,37.5 v1(20.3,37.5)
  LAYER_4 w0.2: v1(23.2,12) 23.2,16.6 22.7,17.1 22.7,26.8 22.38,27.13 22.38,35.62 20.86,37.15 20.66,37.15 v1(20.3,37.5)
  BOTTOM w0.25: v1(20.3,37.5) 20.5,37.5 20.78,37.78 21.05,37.78 C52.2
VTRIM-54: length 29.3
  TOP w0.2: RN18.6 34.15,12.05 34.1,12 v1(34.1,11.5)
  TOP w0.25: v1(37.9,35.28) C54.2
  LAYER_4 w0.2: v1(37.9,35.28) 37.19,35.28 36.3,34.4 36.3,27.3 35.4,26.4 35.4,25.4 35.8,25 35.8,19.4 34.2,17.8 34.2,12.1 34.1,12 v1(34.1,11.5)
  BOTTOM w0.25: C54.2 v1(37.9,35.28)
VTRIM-55: length 15.4
  TOP w0.2: v1(22.1,26.1) 22.1,24.7 23.25,23.55 RN9.6
  TOP w0.25: v1(20.4,34.9) 20.5,34.9 20.84,35.24 21.05,35.24 C56.2
  LAYER_4 w0.2: v1(22.1,26.1) 21.8,26.4 21.8,34.1 21,34.9 v1(20.4,34.9)
  BOTTOM w0.25: v1(20.4,34.9) 20.76,34.9 21.1,35.24 C56.2
VTRIM-56: length 14.4
  TOP w0.2: v1(36.1,25.9) 35.9,25.7 35.9,24.6 34.85,23.55 RN17.6
  TOP w0.25: C58.2 v1(37.9,34.02)
  LAYER_8 w0.2: v1(37.9,34.02) 37.31,34.02 36.6,33.3 36.6,27.1 36.1,26.6 v1(36.1,25.9)
  BOTTOM w0.25: v1(37.9,34.02) C58.2
VTRIM-57: length 26
  TOP w0.2: RN10.6 22.7,12.4 v1(22.25,11.95)
  TOP w0.25: v1(20.4,33.68) 20.77,33.68 C60.2
  LAYER_4 w0.2: v1(20.4,33.68) 20.92,33.68 21.3,33.3 21.3,25.6 22.1,24.8 22.1,16.8 22.4,16.5 22.4,12.6 22.25,12.45 v1(22.25,11.95)
  BOTTOM w0.25: C60.2 21.1,33.99 20.79,33.68 v1(20.4,33.68)
VTRIM-58: length 25.5
  TOP w0.2: v1(34.9,11.8) 34.65,12.05 RN18.7
  TOP w0.25: v1(37.9,32.74) C62.2
  LAYER_4 w0.2: v1(34.9,11.8) 34.9,17.5 36.6,19.2 36.6,25.2 36.83,25.43 36.83,32.23 37.34,32.74 v1(37.9,32.74)
  BOTTOM w0.25: C62.2 v1(37.9,32.74)
VTRIM-59: length 12.7
  TOP w0.2: v1(21.4,24.4) 22.1,23.7 22.33,23.7 22.75,23.28 RN9.7
  TOP w0.25: C64.2 20.75,32.74 20.5,32.5 v1(20.39,32.5)
  LAYER_6 w0.2: v1(20.39,32.5) 20.9,32.5 21.4,32 v1(21.4,24.4)
  BOTTOM w0.25: C64.2 20.85,32.5 v1(20.39,32.5)
VTRIM-60: length 11.7
  TOP w0.2: RN17.5 36,22.8 37.2,24 v1(37.2,24.5)
  TOP w0.25: C66.2 v1(37.9,31.48)
  LAYER_4 w0.2: v1(37.2,24.5) 37.38,24.68 37.38,30.95 v1(37.9,31.48)
  BOTTOM w0.25: v1(37.9,31.48) C66.2
VTRIM-61: length 21.9
  TOP w0.2: v1(21.6,12.6) 21.75,12.6 22.2,13.05 RN10.5
  TOP w0.25: v1(20.39,31.2) 20.82,31.2 C68.2
  LAYER_4 w0.2: v1(20.39,31.2) 20.39,30.19 20.1,29.9 20.1,24.5 21.7,22.9 21.7,13.2 21.6,13.1 v1(21.6,12.6)
  BOTTOM w0.25: C68.2 20.77,31.48 20.5,31.2 v1(20.39,31.2)
VTRIM-62: length 21.7
  TOP w0.2: RN18.8 35.15,12.45 35.3,12.3 v1(35.8,12.3)
  TOP w0.25: v1(37.9,30.2) C70.2
  LAYER_4 w0.2: v1(37.9,30.2) 37.9,19.6 35.8,17.5 v1(35.8,12.3)
  BOTTOM w0.25: C70.2 v1(37.9,30.2)
VTRIM-63: length 9.4
  TOP w0.2: RN9.8 21.72,22.8 20.7,23.82 v1(20.7,29.49)
  TOP w0.25: C72.2 20.7,29.81 v1(20.7,29.49)
  BOTTOM w0.25: v1(20.7,29.49) 20.7,29.6 20.8,29.7 20.8,29.91 C72.2
N919474: length 5.5
  TOP w0.2: IC2.5 12.2,17.6 12,17.4 10.4,17.4 9.4,18.4 IC1.19
N920822: length 44.7
  TOP w0.2: IC2.3 12.3,18.4 11.9,18.8 v1(11.3,18.8) ; IC1.3 3.1,18.4 2.8,18.7 v1(2.3,18.7) ; v1(29.1,19.1) 29.8,18.4 IC4.3 31.6,18.4 ; IC3.3 21.4,18.4 20.9,18.9 v1(20.3,18.9)
  TOP w0.3: R68.1 v1(20.6,13.6)
  LAYER_8 w0.3: v1(20.6,13.6) 20.6,14.15 20.8,14.35 20.8,18.4 v1(20.3,18.9)
  BOTTOM w0.2: v1(2.3,18.7) 6.5,18.7 6.9,18.3 8.8,18.3 9.65,19.16 10.95,19.16 v1(11.3,18.8) 14.1,18.8 14.62,19.32 19.88,19.32 v1(20.3,18.9) 20.9,18.9 21.2,18.6 24.1,18.6 24.95,19.45 28.74,19.45 v1(29.1,19.1)
N920826: length 43.3
  TOP w0.2: v1(2.2,17.7) 2.5,18 IC1.4 ; IC2.4 v1(11.6,18) ; IC4.4 29.5,18 29.1,18.4 v1(28.6,18.4) ; v1(19.7,18.3) 20.2,18.3 20.5,18 IC3.4
  TOP w0.3: v1(19.5,13.89) 19.2,13.59 R69.1
  LAYER_8 w0.3: v1(19.5,13.89) 19.5,14.6 19.7,14.8 v1(19.7,18.3)
  BOTTOM w0.2: v1(28.6,18.4) 28.1,17.9 20.6,17.9 20.2,18.3 v1(19.7,18.3) 19.2,18.3 18.9,18 v1(11.6,18) 11.2,17.6 6.6,17.6 6.14,18.05 2.55,18.05 v1(2.2,17.7)
N920834: length 5.3
  TOP w0.2: IC3.5 19.2,17.6 18.4,18.4 IC2.19
N924645: length 5.3
  TOP w0.2: IC3.19 27.5,18.4 28.3,17.6 IC4.5
N924657: length 7.2
  TOP w0.2: R71.1 36.9,13.43 37.6,14.13 37.6,17.2 36.4,18.4 IC4.19
N1004615: length 4.8
  TOP w0.2: IC1.5 3,17.6 2.5,17.1 R70.1
N1031796: length 3.2
  TOP w0.4: 20.64,7.42 20.64,9.94 R74.2
N1175823: length 1.7
  TOP w0.2: RN4.1 8.15,15.12 7.7,15.57 IC1.14
N1175825: length 1.7
  TOP w0.2: RN4.2 7.65,15.05 7.3,15.4 IC1.13 7.3,16.1
N1175827: length 1.6
  TOP w0.2: RN4.3 7.15,14.98 6.9,15.23 IC1.12
N1175829: length 1.6
  TOP w0.2: IC1.11 6.5,15.13 6.65,14.98 RN4.4
N1175847: length 1.9
  TOP w0.2: RN3.1 6.85,21.25 6.5,20.9 IC1.25
N1175849: length 2
  TOP w0.2: RN3.2 7.35,21.17 6.9,20.72 IC1.24
N1175851: length 2
  TOP w0.2: IC1.23 7.3,20.5 7.85,21.05 RN3.3
N1175853: length 2.1
  TOP w0.2: RN3.4 8.35,20.98 7.7,20.32 IC1.22
N1175887: length 1.6
  TOP w0.2: IC1.10 6.1,15.2 5.75,14.85 RN2.1
N1175889: length 1.7
  TOP w0.2: RN2.2 5.25,15 5.7,15.45 IC1.9
N1175891: length 1.7
  TOP w0.2: RN2.3 4.75,15.12 5.3,15.68 IC1.8
N1175893: length 2.4
  TOP w0.2: IC1.7 4.5,16.47 4.25,16.22 RN2.4
N1175919: length 2.7
  TOP w0.2: RN1.1 4.25,20.35 4.5,20.1 IC1.1
N1175921: length 2
  TOP w0.2: RN1.2 4.75,20.88 5.3,20.32 IC1.28
N1175923: length 2
  TOP w0.2: IC1.27 5.7,20.65 5.25,21.1 RN1.3
N1175925: length 1.9
  TOP w0.2: RN1.4 5.75,21.32 6.1,20.97 IC1.26
N1178151: length 1.9
  TOP w0.2: IC2.25 15.5,21.2 15.85,21.55 RN7.1
N1178153: length 2
  TOP w0.2: IC2.24 15.9,20.82 16.35,21.27 RN7.2
N1178155: length 2
  TOP w0.2: IC2.23 16.3,20.65 16.85,21.2 RN7.3
N1178157: length 2.1
  TOP w0.2: RN7.4 17.35,20.98 16.7,20.32 IC2.22
N1178159: length 2.1
  TOP w0.2: IC2.10 15.1,15.1 14.65,14.65 RN6.1
N1178161: length 2.1
  TOP w0.2: IC2.9 14.7,15.35 14.15,14.8 RN6.2
N1178163: length 2.2
  TOP w0.2: IC2.8 14.3,15.68 13.65,15.03 RN6.3
N1178165: length 2.8
  TOP w0.2: IC2.7 13.5,16.57 13.15,16.22 RN6.4
N1178167: length 2.1
  TOP w0.2: RN8.1 17.2,15.18 16.7,15.68 IC2.14
N1178169: length 2.1
  TOP w0.2: IC2.13 16.3,15.35 16.7,14.95 RN8.2
N1178171: length 2
  TOP w0.2: RN8.3 16.2,14.9 15.9,15.2 IC2.12
N1178173: length 2
  TOP w0.2: IC2.11 15.5,14.9 15.7,14.7 RN8.4
N1178175: length 2.7
  TOP w0.2: IC2.1 13.5,20.1 13.25,20.35 RN5.1
N1178177: length 2
  TOP w0.2: RN5.2 13.75,21.2 14.3,20.65 IC2.28
N1178179: length 2
  TOP w0.2: IC2.27 14.7,20.87 14.25,21.32 RN5.3
N1178181: length 1.9
  TOP w0.2: IC2.26 15.1,21.2 14.75,21.55 RN5.4
N1179923: length 2.1
  TOP w0.2: IC3.10 24.1,14.98 23.7,14.58 RN10.1
N1179925: length 2.1
  TOP w0.2: IC3.9 23.7,15.2 23.2,14.7 RN10.2
N1179927: length 2.1
  TOP w0.2: IC3.8 23.3,15.4 22.7,14.8 RN10.3
N1179929: length 2.8
  TOP w0.2: IC3.7 22.5,16.57 22.2,16.27 RN10.4
N1179931: length 2.1
  TOP w0.2: RN14.1 26.2,15.18 25.7,15.68 IC3.14
N1179933: length 2.1
  TOP w0.2: RN14.2 25.7,14.95 25.3,15.35 IC3.13
N1179935: length 2
  TOP w0.2: RN14.3 25.2,14.8 24.9,15.1 IC3.12
N1179937: length 2
  TOP w0.2: RN14.4 24.7,14.58 24.5,14.78 IC3.11
N1179939: length 2.7
  TOP w0.2: IC3.1 22.5,20.1 22.25,20.35 RN9.1
N1179941: length 2
  TOP w0.2: RN9.2 22.75,20.88 23.3,20.32 IC3.28
N1179943: length 2
  TOP w0.2: IC3.27 23.7,20.65 23.25,21.1 RN9.3
N1179945: length 1.9
  TOP w0.2: RN9.4 23.75,21.32 24.1,20.97 IC3.26
N1179947: length 1.9
  TOP w0.2: IC3.25 24.5,21.07 24.75,21.32 RN13.1
N1179949: length 1.9
  TOP w0.2: IC3.24 24.9,20.8 25.25,21.15 RN13.2
N1179951: length 2
  TOP w0.2: IC3.23 25.3,20.5 25.75,20.95 RN13.3
N1179953: length 2
  TOP w0.2: RN13.4 26.25,20.88 25.7,20.32 IC3.22
N1180213: length 2.1
  TOP w0.2: IC4.14 34.7,15.68 35.15,15.22 RN18.1
N1180215: length 2
  TOP w0.2: IC4.13 34.3,15.35 34.65,15 RN18.2
N1180217: length 2
  TOP w0.2: RN18.3 34.15,14.85 33.9,15.1 IC4.12
N1180219: length 2
  TOP w0.2: IC4.11 33.5,14.73 33.65,14.58 RN18.4
N1180221: length 2.7
  TOP w0.2: IC4.1 31.5,20.1 31.25,20.35 RN15.1
N1180223: length 2
  TOP w0.2: IC4.28 32.3,20.32 31.75,20.88 RN15.2
N1180225: length 2
  TOP w0.2: RN15.3 32.25,21.15 32.7,20.7 IC4.27
N1180227: length 1.9
  TOP w0.2: RN15.4 32.75,21.32 33.1,20.97 IC4.26
N1180229: length 1.9
  TOP w0.2: RN17.1 33.85,21.55 33.5,21.2 IC4.25
N1180231: length 2
  TOP w0.2: RN17.2 34.35,21.32 33.9,20.87 IC4.24
N1180233: length 2
  TOP w0.2: RN17.3 34.85,21.2 34.3,20.65 IC4.23
N1180235: length 2.1
  TOP w0.2: RN17.4 35.35,20.98 34.7,20.32 IC4.22
N1180237: length 2
  TOP w0.2: IC4.10 33.1,15.05 32.75,14.7 RN16.1
N1180239: length 2.1
  TOP w0.2: IC4.9 32.7,15.35 32.25,14.9 RN16.2
N1180241: length 2.1
  TOP w0.2: RN16.3 31.75,15.12 32.3,15.68 IC4.8
N1180243: length 2.8
  TOP w0.2: RN16.4 31.25,16.15 31.5,16.4 IC4.7

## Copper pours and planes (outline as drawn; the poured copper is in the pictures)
0 on TOP: 1.7,69.4 38.3,69.4 38.3,27 1.7,27
0 on TOP: 33.4,9.5 33.8,9.9 37.2,9.9 37.9,9.2 37.9,1.4 37.3,0.8 34.7,0.8 33.4,2.1
0 on TOP: 2.1,10.1 4.4,10.1 5.1,9.4 5.1,1.6 4.2,0.7 2.5,0.7 1.9,1.3 1.9,9.9
0 on BOTTOM: 1.5,69.4 38.5,69.4 38.5,0.4 1.5,0.4
0 on LAYER_1, LAYER_3, LAYER_5, LAYER_7: 0.5,69.4 39.5,69.4 39.5,0.4 0.5,0.4

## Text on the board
Ref Des/Silkscreen Bottom: AC64_MR_v3 | INFN FE | 19/01/2023
Ref Des/Silkscreen Top: AC64v3 | INFN
XSECTION_CHART: *  SURFACE | *  DIELECTRIC | L1 TOP CONDUCTOR | L2 LAYER_1 PLANE | L3 LAYER_2 CONDUCTOR | L4 LAYER_3 PLANE | L5 LAYER_4 CONDUCTOR | L6 LAYER_5 PLANE | L7 LAYER_6 CONDUCTOR | L8 LAYER_7 PLANE | L9 LAYER_8 CONDUCTOR | L10 BOTTOM CONDUCTOR | STACKUP TABLE | Unit = Millimeter | DESIGN CROSS SECTION CHART | ___________________________ | TOTAL THICKNESS 1.58696 MM | # | 1 | 2 | 3 | 4 | 5 | 6 | 7 | 8 | 9 | 10 | NAME | TOP | LAYER_1 | LAYER_2 | LAYER_3 | LAYER_4 | LAYER_5 | LAYER_6 | LAYER_7 | LAYER_8 | BOTTOM | TYPE | SURFACE | DIELECTRIC | CONDUCTOR | PLANE | MATERIAL | AIR | SOLDERMASK | COPPER | FR-4 | TOTAL THICKNESS | THICKNESS | 0 | 0.02 | 0.0305 | 0.11 | 0.017 | 0.15 | 0.21 | 1.587 | TOLERANCE | +0/-0 | 1-10
DIMENSION: FIGURE | FINISHED_SIZE | 0.25 | 0.254 | 0.965 | 1.0 | 1.02 | DRILL CHART: TOP to BOTTOM | ALL UNITS ARE IN MILLIMETERS | PLATED | NON-PLATED | QTY | 355 | 2 | 94 | 4
